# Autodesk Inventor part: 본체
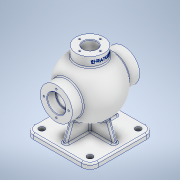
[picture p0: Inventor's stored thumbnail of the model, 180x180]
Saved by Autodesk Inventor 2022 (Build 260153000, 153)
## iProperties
Created: 2024-04
Part Number: 본체
Material: 알루미늄 6061
Document SubType Name: Modeling
Designer: Admin
Mass: 1526.72 g
Surface Area: 1173.82 cm^2
Volume: 565.453 cm^3
Density: 2.7 g/cm^3
Appearance: 알루미늄 - 평지
Author: Admin
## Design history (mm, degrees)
sketch "스케치1"
  geometry: L1 (-75.6, 0)-(75.6, 0) reference; L2 (0, -75.6)-(0, 75.6) reference; L3 (0, 54)-(0, -54); A1 r 54 centre (0, 0) between (0, 54) and (0, -54); 1 further point
  constraints: 2 end point, 2 point on circle, 2 point on line, 1 centre point, 1 coincident
  dimensions: "d1" = 54 radius of A1
revolve "회전1" sketch "스케치1" stored, may be unused: angle "d2" = 90 deg
node "작업 평면1"
sketch "스케치2"
  geometry: L1 (-62.5, -62.5)-(62.5, -62.5); L2 (62.5, -62.5)-(62.5, 62.5); L3 (62.5, 62.5)-(-62.5, 62.5); L4 (-62.5, 62.5)-(-62.5, -62.5); L5 (-62.5, -62.5)-(62.5, 62.5); L6 (62.5, -62.5)-(-62.5, 62.5); 1 further point
  constraints: 12 end point, 2 midpoint, 2 parallel, 1 horizontal, 1 perpendicular
  dimensions: "d4" = 125 distance of L1.end L2.end; "d5" = 125 distance of L2.end L3.end
extrude "돌출1" join sketch "스케치2" distance "d6" = 10; taper "d7" = 0 deg
sketch "스케치3"
  geometry: L1 (-75, 50.5)-(0, 23.202); L2 (0, 23.202)-(0, -23.202); L3 (0, -23.202)-(-75, -50.5); L4 (-75, -62.5)-(-75, 62.5) reference; L5 (-75, 50.5)-(-75, -50.5); L6 (-85, 62.5)-(-75, 62.5) reference; L7 (-85, -62.5)-(-75, -62.5) reference; 2 further points
  constraints: 8 end point, 1 collinear, 1 midpoint, 1 point on line, 1 vertical
  dimensions: "d8" = 20 deg angle of L1 L6; "d9" = 20 deg angle of L7 L3; "d10" = 12 distance from line of L7 L3.end; "d11" = 12 distance from line of L6 L1.start
extrude "돌출2" join sketch "스케치3" stored distance "d12" = 8; taper "d13" = 0 deg
sketch "스케치4"
  geometry: L1 (62.5, -75)-(-62.5, -75) reference; L2 (-50.5, -75)-(-23.202, 0); L3 (-23.202, 0)-(23.202, 0); L4 (23.202, 0)-(50.5, -75); L5 (-50.5, -75)-(50.5, -75); L6 (-62.5, -85)-(-62.5, -75) reference; L7 (62.5, -85)-(62.5, -75) reference; 1 further point
  constraints: 8 end point, 2 parallel, 2 point on line, 1 midpoint
  dimensions: "d14" = 20 deg angle of L6 L2; "d15" = 20 deg angle of L7 L4; "d16" = 12 distance from line of L7 L4.end; "d17" = 12 distance from line of L6 L2.start
extrude "돌출3" join sketch "스케치4" stored distance "d18" = 8; taper "d19" = 0 deg
node "작업 평면2"
sketch "스케치5"
  geometry: C1 r 27 at (0, 0); 1 further point
  constraints: 1 centre point, 1 coincident
  dimensions: "d21" = 54 diameter of C1
extrude "돌출4" join sketch "스케치5" stored distance "d22" = 8; taper "d23" = 0 deg
node "작업 평면3"
sketch "스케치6"
  geometry: C1 r 31 at (0, 0); 1 further point
  constraints: 1 centre point, 1 coincident
  dimensions: "d25" = 62 diameter of C1
extrude "돌출5" join sketch "스케치6" stored distance "d26" = 10; taper "d27" = 0 deg
sketch "스케치7"
  geometry: L1 (-31, 44.215)-(31, 44.215) reference; L2 (0, 44.215)-(0, -44.215); L3 (31, -44.215)-(-31, -44.215) reference; C1 r 44 at (0, 0); 3 further points
  constraints: 2 end point, 2 midpoint, 1 centre point, 1 coincident
  dimensions: "d29" = 44 radius of C1
revolve "회전2" sketch "스케치7" stored, may be unused: angle "d30" = 90 deg
sketch "스케치8"
  geometry: C1 r 17.5 at (0, 0); 1 further point
  constraints: 1 centre point, 1 coincident
  dimensions: "d31" = 35 diameter of C1
extrude "돌출6" cut sketch "스케치8" distance "d32" = 16; taper "d33" = 0 deg
sketch "스케치9"
  geometry: C1 r 15 at (0, 0); 1 further point
  constraints: 1 centre point, 1 coincident
  dimensions: "d34" = 30 diameter of C1
extrude "돌출7" cut sketch "스케치9" stored distance "d35" = 16; taper "d36" = 0 deg
fillet "모깎기1" dims "d37" = 0.6
chamfer "모따기1" distance "d38" = 1; stored, may be unused: second distance "d39" = 2, angle "d40" = 45 deg
sketch "스케치10"
  geometry: C1 r 13 at (0, 0); 1 further point
  constraints: 1 centre point, 1 coincident
  dimensions: "d41" = 26 diameter of C1
extrude "돌출8" cut sketch "스케치10" stored distance "d42" = 10; taper "d43" = 0 deg
fillet "모깎기2" dims "d44" = 16
sketch "스케치11"
  geometry: C1 r 5.5 at (-46.5, 46.5); C2 r 5.5 at (46.5, 46.5); C3 r 5.5 at (46.5, -46.5); C4 r 5.5 at (-46.5, -46.5); A1 r 16 centre (-46.5, 46.5) between (-46.5, 62.5) and (-62.5, 46.5) reference; A2 r 16 centre (46.5, 46.5) between (62.5, 46.5) and (46.5, 62.5) reference; A3 r 16 centre (46.5, -46.5) between (46.5, -62.5) and (62.5, -46.5) reference; A4 r 16 centre (-46.5, -46.5) between (-62.5, -46.5) and (-46.5, -62.5) reference; 1 further point
  constraints: 4 centre point, 4 coincident
  dimensions: "d45" = 11 diameter of C1; "d46" = 11 diameter of C2 (= d45); "d47" = 11 diameter of C3 (= d46); "d48" = 11 diameter of C4 (= d45)
extrude "돌출9" cut sketch "스케치11" extent not by distance; stored distance "d49" = 10; taper "d50" = 0 deg
sketch "스케치12"
  geometry: 5 further points
  constraints: 1 vertical alignment, 5 other
  dimensions: "d51" = 24 distance of point (0, 0) point (0, 24); "d54" = 360 deg dimension on point (0, 0) point (0, 24) (derived)
hole "구멍1" sketch "스케치12" at (0, 24), (-24, 0), (0, -24), (24, 0) diameter "d56" = 3.242; stored, may be unused: countersink angle "d60" = 90 deg, drill point angle "d62" = 118 deg; dims "d57" = 12, "d58" = 4, "d59" = 2, "d61" = 15
sketch "스케치13"
  geometry: 5 further points
  constraints: 1 horizontal alignment, 5 other
  dimensions: "d63" = 20 distance of point (0, 0) point (-20, 0); "d66" = 360 deg dimension on point (0, 0) point (-20, 0) (derived)
hole "구멍2" sketch "스케치13" at (-20, 0), (0, -20), (20, 0), (0, 20) diameter "d68" = 3.242; stored, may be unused: countersink angle "d72" = 90 deg, drill point angle "d74" = 118 deg; dims "d69" = 9, "d70" = 4, "d71" = 2, "d73" = 11
chamfer "모따기2" distance "d75" = 1; stored, may be unused: second distance "d76" = 2, angle "d77" = 45 deg
node "작업 평면4"
sketch "스케치14"
  geometry: L1 (0, 27)-(0, -27) reference; L2 (-180, 0)-(30, 0) reference; 2 further points
  constraints: 1 point on line, 1 other
  dimensions: "d78" = 9 distance from line of point (-9, 0) L1
feature "엠보싱1" sketch "스케치14" dims "d1" = 54, "d8" = 20 deg, "d9" = 20 deg, "d10" = 12, "d11" = 12, "d79" = 0.5, "d80" = 0
fillet "모깎기3" dims "d81" = 3
fillet "모깎기4" dims "d82" = 3
fillet "모깎기5" dims "d83" = 3
node "솔리드1"
mirror "미러1"
mirror "미러2"
mirror "미러3"
feature "A9D066F2-1C7D-4E18-AEED-F7BC21143FA4" dims "d56" = 3.242, "d57" = 12, "d58" = 4, "d59" = 2, "d60" = 90 deg, "d61" = 15, "d62" = 118 deg
other parameters: "d3" = -85, "d24" = 65
